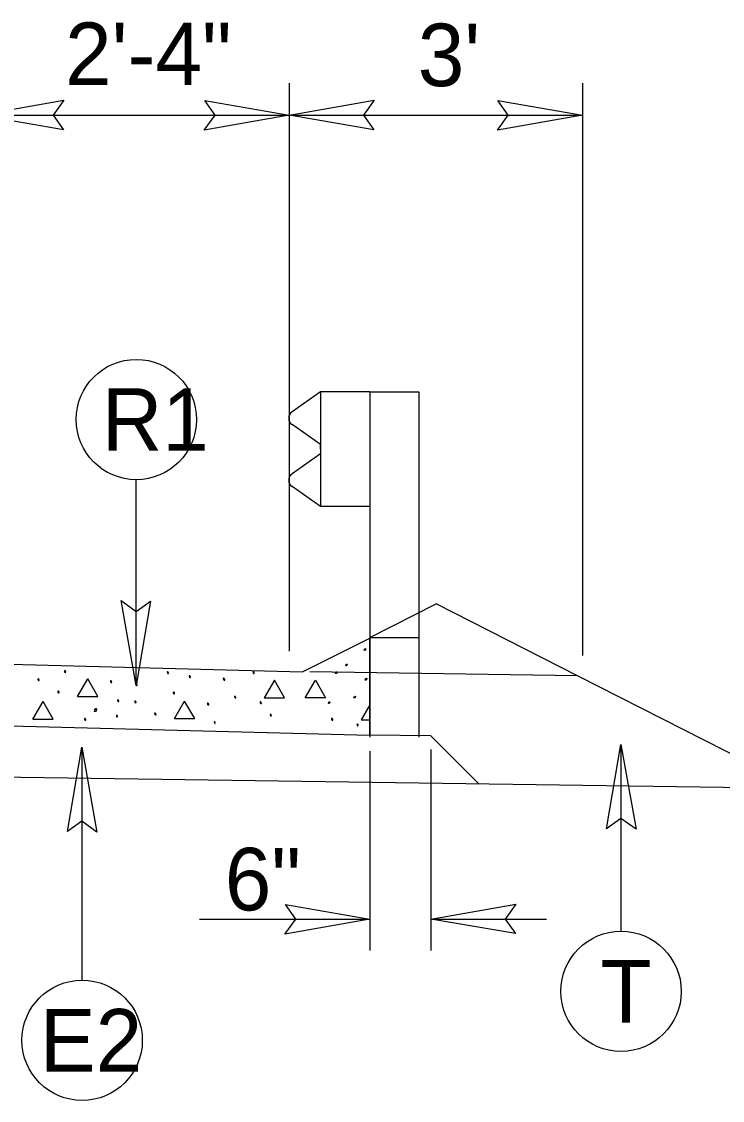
# Model space of a CAD drawing. Extents: x 1553884 to 1554215, y 810431 to 810779.
# Drawn here: x 1554046.03 to 1554057.23, y 810663.89 to 810681.15 of the extents above; entities that cross this region are included whole.
import ezdxf

# ---------------------------------------------------------------- set-up
doc = ezdxf.new("R2010")
doc.units = 0
for name, color, linetype in [('Old_Level_1', 7, 'Continuous'), ('Prop CMT Steel Beam Girder', 7, 'Continuous'), ('Prop Shade Light', 7, 'Continuous'), ('Typical Detail Pavement Repair CELL', 7, 'Continuous'), ('Typical Guardrail CELL', 7, 'Continuous'), ('Typical Pavement Slope Information CELL', 7, 'Continuous'), ('Typical Text ID Circle CELL', 7, 'Continuous')]:
    doc.layers.add(name, color=color, linetype=linetype)

msp = doc.modelspace()

# ---------------------------------------------------------------- linework, layer by layer
at = {"layer": 'Old_Level_1'}
for p, q in [((1554050.307, 810680.165), (1554050.307, 810671.075)), ((1554054.993, 810680.165), (1554054.993, 810671.007)), ((1554045.346, 810679.651), (1554050.307, 810679.651)), ((1554050.307, 810679.651), (1554054.993, 810679.651)), ((1554051.595, 810671.296), (1554052.655, 810671.836)), ((1554054.916, 810670.684), (1554052.655, 810671.836)), ((1554051.506, 810671.092), (1554051.511, 810671.107)), ((1554051.511, 810671.107), (1554051.52, 810671.112)), ((1554051.512, 810671.11), (1554051.517, 810671.114)), ((1554051.517, 810671.114), (1554051.525, 810671.117)), ((1554051.525, 810671.117), (1554051.528, 810671.11)), ((1554051.526, 810671.106), (1554051.525, 810671.093)), ((1554051.528, 810671.106), (1554051.526, 810671.106)), ((1554051.528, 810671.11), (1554051.528, 810671.106)), ((1554051.506, 810671.09), (1554051.506, 810671.092)), ((1554051.517, 810671.087), (1554051.506, 810671.09)), ((1554051.525, 810671.093), (1554051.517, 810671.087)), ((1554046.716, 810670.765), (1554046.713, 810670.759)), ((1554046.713, 810670.759), (1554046.713, 810670.754)), ((1554046.713, 810670.754), (1554046.715, 810670.754)), ((1554046.715, 810670.754), (1554046.716, 810670.743)), ((1554046.725, 810670.764), (1554046.716, 810670.765)), ((1554046.73, 810670.758), (1554046.721, 810670.761)), ((1554046.729, 810670.759), (1554046.725, 810670.764)), ((1554046.735, 810670.74), (1554046.73, 810670.758)), ((1554051.212, 810670.847), (1554051.215, 810670.862)), ((1554051.212, 810670.845), (1554051.212, 810670.847)), ((1554051.221, 810670.842), (1554051.212, 810670.845)), ((1554051.215, 810670.862), (1554051.226, 810670.867)), ((1554051.218, 810670.865), (1554051.221, 810670.868)), ((1554051.221, 810670.868), (1554051.229, 810670.871)), ((1554051.229, 810670.848), (1554051.221, 810670.842)), ((1554051.229, 810670.871), (1554051.234, 810670.865)), ((1554051.232, 810670.861), (1554051.229, 810670.848)), ((1554051.234, 810670.861), (1554051.232, 810670.861)), ((1554051.234, 810670.865), (1554051.234, 810670.861)), ((1554046.293, 810670.634), (1554046.288, 810670.628)), ((1554046.288, 810670.628), (1554046.288, 810670.625)), ((1554046.288, 810670.625), (1554046.29, 810670.625)), ((1554046.29, 810670.625), (1554046.293, 810670.612)), ((1554046.301, 810670.633), (1554046.293, 810670.634)), ((1554046.293, 810670.612), (1554046.301, 810670.606)), ((1554046.307, 810670.626), (1554046.296, 810670.631)), ((1554046.304, 810670.628), (1554046.301, 810670.633)), ((1554046.301, 810670.606), (1554046.31, 810670.607)), ((1554046.31, 810670.611), (1554046.307, 810670.626)), ((1554046.31, 810670.607), (1554046.31, 810670.611)), ((1554046.716, 810670.743), (1554046.725, 810670.737)), ((1554046.725, 810670.737), (1554046.735, 810670.739)), ((1554046.735, 810670.739), (1554046.735, 810670.74)), ((1554046.922, 810670.351), (1554047.085, 810670.633)), ((1554047.247, 810670.351), (1554047.085, 810670.633)), ((1554047.452, 810670.601), (1554047.447, 810670.595)), ((1554047.447, 810670.595), (1554047.447, 810670.592)), ((1554047.447, 810670.592), (1554047.45, 810670.592)), ((1554047.45, 810670.592), (1554047.452, 810670.579)), ((1554047.46, 810670.6), (1554047.452, 810670.601)), ((1554047.466, 810670.594), (1554047.455, 810670.598)), ((1554047.464, 810670.595), (1554047.46, 810670.6)), ((1554047.471, 810670.578), (1554047.466, 810670.594)), ((1554048.358, 810670.748), (1554048.353, 810670.742)), ((1554048.353, 810670.742), (1554048.353, 810670.739)), ((1554048.353, 810670.739), (1554048.356, 810670.739)), ((1554048.356, 810670.739), (1554048.358, 810670.726)), ((1554048.366, 810670.747), (1554048.358, 810670.748)), ((1554048.358, 810670.726), (1554048.366, 810670.72)), ((1554048.372, 810670.74), (1554048.361, 810670.745)), ((1554048.37, 810670.742), (1554048.366, 810670.747)), ((1554048.366, 810670.72), (1554048.377, 810670.722)), ((1554048.377, 810670.725), (1554048.372, 810670.74)), ((1554048.377, 810670.722), (1554048.377, 810670.725)), ((1554048.709, 810670.684), (1554048.705, 810670.678)), ((1554048.705, 810670.678), (1554048.705, 810670.673)), ((1554048.705, 810670.673), (1554048.706, 810670.673)), ((1554048.706, 810670.673), (1554048.709, 810670.661)), ((1554048.717, 810670.681), (1554048.709, 810670.684)), ((1554048.709, 810670.661), (1554048.717, 810670.654)), ((1554048.723, 810670.675), (1554048.713, 810670.679)), ((1554048.72, 810670.678), (1554048.717, 810670.681)), ((1554048.717, 810670.654), (1554048.727, 810670.658)), ((1554048.727, 810670.659), (1554048.723, 810670.675)), ((1554048.727, 810670.658), (1554048.727, 810670.659)), ((1554049.256, 810670.644), (1554049.251, 810670.637)), ((1554049.251, 810670.637), (1554049.251, 810670.633)), ((1554049.251, 810670.633), (1554049.255, 810670.633)), ((1554049.255, 810670.633), (1554049.256, 810670.62)), ((1554049.264, 810670.64), (1554049.256, 810670.644)), ((1554049.256, 810670.62), (1554049.264, 810670.614)), ((1554049.27, 810670.634), (1554049.259, 810670.639)), ((1554049.269, 810670.637), (1554049.264, 810670.64)), ((1554049.264, 810670.614), (1554049.275, 810670.615)), ((1554049.275, 810670.619), (1554049.27, 810670.634)), ((1554049.275, 810670.615), (1554049.275, 810670.619)), ((1554049.729, 810670.748), (1554049.725, 810670.742)), ((1554049.725, 810670.742), (1554049.725, 810670.739)), ((1554049.725, 810670.739), (1554049.728, 810670.739)), ((1554049.728, 810670.739), (1554049.729, 810670.726)), ((1554049.737, 810670.747), (1554049.729, 810670.748)), ((1554049.729, 810670.726), (1554049.737, 810670.72)), ((1554049.744, 810670.74), (1554049.734, 810670.745)), ((1554049.742, 810670.742), (1554049.737, 810670.747)), ((1554049.737, 810670.72), (1554049.748, 810670.722)), ((1554049.748, 810670.725), (1554049.744, 810670.74)), ((1554049.748, 810670.722), (1554049.748, 810670.725)), ((1554050.07, 810670.612), (1554049.908, 810670.331)), ((1554050.233, 810670.331), (1554050.07, 810670.612)), ((1554050.564, 810670.331), (1554050.726, 810670.612)), ((1554054.916, 810670.684), (1554050.634, 810670.747)), ((1554050.726, 810670.612), (1554050.889, 810670.331)), ((1554051.048, 810670.725), (1554051.053, 810670.74)), ((1554051.048, 810670.722), (1554051.048, 810670.725)), ((1554051.059, 810670.72), (1554051.048, 810670.722)), ((1554051.053, 810670.74), (1554051.062, 810670.745)), ((1554051.054, 810670.742), (1554051.059, 810670.747)), ((1554051.059, 810670.747), (1554051.067, 810670.748)), ((1554051.067, 810670.726), (1554051.059, 810670.72)), ((1554051.067, 810670.748), (1554051.072, 810670.742)), ((1554051.068, 810670.739), (1554051.067, 810670.726)), ((1554051.072, 810670.739), (1554051.068, 810670.739)), ((1554051.072, 810670.742), (1554051.072, 810670.739)), ((1554051.522, 810670.619), (1554051.526, 810670.634)), ((1554051.522, 810670.615), (1554051.522, 810670.619)), ((1554051.532, 810670.614), (1554051.522, 810670.615)), ((1554051.526, 810670.634), (1554051.535, 810670.639)), ((1554051.528, 810670.637), (1554051.532, 810670.64)), ((1554051.532, 810670.64), (1554051.54, 810670.644)), ((1554051.54, 810670.62), (1554051.532, 810670.614)), ((1554051.54, 810670.644), (1554051.545, 810670.637)), ((1554051.542, 810670.633), (1554051.54, 810670.62)), ((1554051.545, 810670.633), (1554051.542, 810670.633)), ((1554051.545, 810670.637), (1554051.545, 810670.633)), ((1554062.264, 810666.94), (1554054.916, 810670.684)), ((1554046.61, 810670.439), (1554046.607, 810670.433)), ((1554046.607, 810670.433), (1554046.607, 810670.428)), ((1554046.607, 810670.428), (1554046.608, 810670.428)), ((1554046.608, 810670.428), (1554046.61, 810670.415)), ((1554046.619, 810670.437), (1554046.61, 810670.439)), ((1554046.61, 810670.415), (1554046.619, 810670.411)), ((1554046.625, 810670.431), (1554046.614, 810670.434)), ((1554046.622, 810670.433), (1554046.619, 810670.437)), ((1554046.619, 810670.411), (1554046.629, 810670.412)), ((1554046.629, 810670.414), (1554046.625, 810670.431)), ((1554046.629, 810670.412), (1554046.629, 810670.414)), ((1554047.452, 810670.579), (1554047.46, 810670.573)), ((1554047.46, 810670.573), (1554047.471, 810670.575)), ((1554047.471, 810670.575), (1554047.471, 810670.578)), ((1554047.86, 810670.553), (1554047.857, 810670.547)), ((1554047.857, 810670.547), (1554047.857, 810670.542)), ((1554047.857, 810670.542), (1554047.858, 810670.542)), ((1554047.858, 810670.542), (1554047.86, 810670.531)), ((1554047.867, 810670.551), (1554047.86, 810670.553)), ((1554047.86, 810670.531), (1554047.867, 810670.525)), ((1554047.874, 810670.545), (1554047.864, 810670.548)), ((1554047.872, 810670.547), (1554047.867, 810670.551)), ((1554047.867, 810670.525), (1554047.878, 810670.526)), ((1554047.878, 810670.528), (1554047.874, 810670.545)), ((1554047.878, 810670.526), (1554047.878, 810670.528)), ((1554048.456, 810670.422), (1554048.452, 810670.415)), ((1554048.452, 810670.415), (1554048.452, 810670.412)), ((1554048.452, 810670.412), (1554048.453, 810670.412)), ((1554048.453, 810670.412), (1554048.456, 810670.4)), ((1554048.464, 810670.42), (1554048.456, 810670.422)), ((1554048.47, 810670.414), (1554048.459, 810670.419)), ((1554048.467, 810670.415), (1554048.464, 810670.42)), ((1554048.474, 810670.398), (1554048.47, 810670.414)), ((1554046.21, 810669.987), (1554046.372, 810670.269)), ((1554046.535, 810669.987), (1554046.372, 810670.269)), ((1554046.922, 810670.351), (1554047.247, 810670.351)), ((1554047.566, 810670.3), (1554047.561, 810670.294)), ((1554047.561, 810670.294), (1554047.561, 810670.289)), ((1554047.561, 810670.289), (1554047.564, 810670.289)), ((1554047.564, 810670.289), (1554047.566, 810670.278)), ((1554047.574, 810670.298), (1554047.566, 810670.3)), ((1554047.566, 810670.278), (1554047.574, 810670.272)), ((1554047.58, 810670.292), (1554047.569, 810670.295)), ((1554047.578, 810670.294), (1554047.574, 810670.298)), ((1554047.574, 810670.272), (1554047.585, 810670.273)), ((1554047.585, 810670.275), (1554047.58, 810670.292)), ((1554047.585, 810670.273), (1554047.585, 810670.275)), ((1554047.841, 810670.28), (1554047.836, 810670.273)), ((1554047.836, 810670.273), (1554047.836, 810670.27)), ((1554047.836, 810670.27), (1554047.838, 810670.27)), ((1554047.838, 810670.27), (1554047.841, 810670.258)), ((1554047.849, 810670.278), (1554047.841, 810670.28)), ((1554047.841, 810670.258), (1554047.849, 810670.252)), ((1554047.855, 810670.272), (1554047.844, 810670.277)), ((1554047.852, 810670.273), (1554047.849, 810670.278)), ((1554047.849, 810670.252), (1554047.858, 810670.253)), ((1554047.858, 810670.256), (1554047.855, 810670.272)), ((1554047.858, 810670.253), (1554047.858, 810670.256)), ((1554048.456, 810670.4), (1554048.464, 810670.394)), ((1554048.464, 810670.394), (1554048.474, 810670.395)), ((1554048.471, 810669.997), (1554048.633, 810670.278)), ((1554048.474, 810670.395), (1554048.474, 810670.398)), ((1554048.796, 810669.997), (1554048.633, 810670.278)), ((1554049, 810670.247), (1554048.996, 810670.24)), ((1554048.996, 810670.24), (1554048.996, 810670.237)), ((1554048.996, 810670.237), (1554048.999, 810670.237)), ((1554048.999, 810670.237), (1554049, 810670.225)), ((1554049.008, 810670.245), (1554049, 810670.247)), ((1554049.014, 810670.239), (1554049.003, 810670.244)), ((1554049.013, 810670.24), (1554049.008, 810670.245)), ((1554049.019, 810670.223), (1554049.014, 810670.239)), ((1554049.436, 810670.358), (1554049.431, 810670.351)), ((1554049.431, 810670.351), (1554049.431, 810670.347)), ((1554049.431, 810670.347), (1554049.434, 810670.347)), ((1554049.434, 810670.347), (1554049.436, 810670.334)), ((1554049.444, 810670.354), (1554049.436, 810670.358)), ((1554049.436, 810670.334), (1554049.444, 810670.328)), ((1554049.45, 810670.348), (1554049.439, 810670.353)), ((1554049.448, 810670.351), (1554049.444, 810670.354)), ((1554049.444, 810670.328), (1554049.455, 810670.33)), ((1554049.455, 810670.333), (1554049.45, 810670.348)), ((1554049.455, 810670.33), (1554049.455, 810670.333)), ((1554049.844, 810670.267), (1554049.841, 810670.261)), ((1554049.841, 810670.261), (1554049.841, 810670.258)), ((1554049.841, 810670.258), (1554049.842, 810670.258)), ((1554049.842, 810670.258), (1554049.844, 810670.245)), ((1554049.851, 810670.265), (1554049.844, 810670.267)), ((1554049.844, 810670.245), (1554049.851, 810670.239)), ((1554049.858, 810670.259), (1554049.848, 810670.262)), ((1554049.856, 810670.261), (1554049.851, 810670.265)), ((1554049.851, 810670.239), (1554049.862, 810670.24)), ((1554049.862, 810670.242), (1554049.858, 810670.259)), ((1554049.862, 810670.24), (1554049.862, 810670.242)), ((1554049.908, 810670.331), (1554050.233, 810670.331)), ((1554050.889, 810670.331), (1554050.564, 810670.331)), ((1554050.934, 810670.242), (1554050.939, 810670.259)), ((1554050.934, 810670.24), (1554050.934, 810670.242)), ((1554050.945, 810670.239), (1554050.934, 810670.24)), ((1554050.939, 810670.259), (1554050.948, 810670.262)), ((1554050.94, 810670.261), (1554050.945, 810670.265)), ((1554050.945, 810670.265), (1554050.953, 810670.267)), ((1554050.953, 810670.245), (1554050.945, 810670.239)), ((1554050.953, 810670.267), (1554050.956, 810670.261)), ((1554050.954, 810670.258), (1554050.953, 810670.245)), ((1554050.956, 810670.258), (1554050.954, 810670.258)), ((1554050.956, 810670.261), (1554050.956, 810670.258)), ((1554051.342, 810670.333), (1554051.347, 810670.348)), ((1554051.342, 810670.33), (1554051.342, 810670.333)), ((1554051.353, 810670.328), (1554051.342, 810670.33)), ((1554051.347, 810670.348), (1554051.358, 810670.353)), ((1554051.348, 810670.351), (1554051.353, 810670.354)), ((1554051.353, 810670.354), (1554051.361, 810670.358)), ((1554051.361, 810670.334), (1554051.353, 810670.328)), ((1554051.361, 810670.358), (1554051.365, 810670.351)), ((1554051.362, 810670.347), (1554051.361, 810670.334)), ((1554051.365, 810670.347), (1554051.362, 810670.347)), ((1554051.365, 810670.351), (1554051.365, 810670.347)), ((1554047.196, 810670.114), (1554047.197, 810670.129)), ((1554047.199, 810670.111), (1554047.196, 810670.114)), ((1554047.197, 810670.129), (1554047.199, 810670.131)), ((1554047.199, 810670.145), (1554047.204, 810670.153)), ((1554047.199, 810670.147), (1554047.202, 810670.153)), ((1554047.202, 810670.153), (1554047.199, 810670.137)), ((1554047.202, 810670.131), (1554047.199, 810670.147)), ((1554047.199, 810670.126), (1554047.199, 810670.145)), ((1554047.199, 810670.131), (1554047.202, 810670.131)), ((1554047.212, 810670.114), (1554047.199, 810670.111)), ((1554047.204, 810670.153), (1554047.216, 810670.158)), ((1554047.219, 810670.119), (1554047.212, 810670.114)), ((1554047.216, 810670.158), (1554047.222, 810670.158)), ((1554047.218, 810670.144), (1554047.216, 810670.141)), ((1554047.216, 810670.141), (1554047.218, 810670.139)), ((1554047.226, 810670.145), (1554047.218, 810670.144)), ((1554047.218, 810670.139), (1554047.224, 810670.126)), ((1554047.224, 810670.126), (1554047.219, 810670.119)), ((1554047.222, 810670.158), (1554047.226, 810670.153)), ((1554047.226, 810670.153), (1554047.226, 810670.145)), ((1554048.158, 810670.084), (1554048.155, 810670.078)), ((1554048.155, 810670.078), (1554048.155, 810670.073)), ((1554048.155, 810670.073), (1554048.157, 810670.073)), ((1554048.157, 810670.073), (1554048.158, 810670.061)), ((1554048.167, 810670.083), (1554048.158, 810670.084)), ((1554048.174, 810670.076), (1554048.163, 810670.08)), ((1554048.171, 810670.078), (1554048.167, 810670.083)), ((1554048.177, 810670.059), (1554048.174, 810670.076)), ((1554049, 810670.225), (1554049.008, 810670.218)), ((1554049.008, 810670.218), (1554049.019, 810670.22)), ((1554049.019, 810670.22), (1554049.019, 810670.223)), ((1554050.005, 810670.067), (1554050, 810670.061)), ((1554050.012, 810670.065), (1554050.005, 810670.067)), ((1554050.019, 810670.059), (1554050.008, 810670.064)), ((1554050.016, 810670.061), (1554050.012, 810670.065)), ((1554051.595, 810670.217), (1554051.456, 810669.976)), ((1554046.21, 810669.987), (1554046.535, 810669.987)), ((1554047.036, 810670), (1554047.033, 810669.994)), ((1554047.033, 810669.994), (1554047.033, 810669.991)), ((1554047.033, 810669.991), (1554047.035, 810669.991)), ((1554047.035, 810669.991), (1554047.036, 810669.978)), ((1554047.046, 810669.998), (1554047.036, 810670)), ((1554047.036, 810669.978), (1554047.046, 810669.972)), ((1554047.052, 810669.992), (1554047.041, 810669.997)), ((1554047.049, 810669.994), (1554047.046, 810669.998)), ((1554047.046, 810669.972), (1554047.055, 810669.973)), ((1554047.055, 810669.976), (1554047.052, 810669.992)), ((1554047.055, 810669.973), (1554047.055, 810669.976)), ((1554047.546, 810670.052), (1554047.543, 810670.045)), ((1554047.543, 810670.045), (1554047.543, 810670.041)), ((1554047.543, 810670.041), (1554047.544, 810670.041)), ((1554047.544, 810670.041), (1554047.546, 810670.03)), ((1554047.555, 810670.05), (1554047.546, 810670.052)), ((1554047.546, 810670.03), (1554047.555, 810670.023)), ((1554047.561, 810670.044), (1554047.55, 810670.047)), ((1554047.558, 810670.045), (1554047.555, 810670.05)), ((1554047.555, 810670.023), (1554047.564, 810670.025)), ((1554047.564, 810670.026), (1554047.561, 810670.044)), ((1554047.564, 810670.025), (1554047.564, 810670.026)), ((1554048.158, 810670.061), (1554048.167, 810670.056)), ((1554048.167, 810670.056), (1554048.177, 810670.058)), ((1554048.177, 810670.058), (1554048.177, 810670.059)), ((1554048.471, 810669.997), (1554048.796, 810669.997)), ((1554049.114, 810669.945), (1554049.109, 810669.939)), ((1554049.109, 810669.939), (1554049.109, 810669.934)), ((1554049.109, 810669.934), (1554049.113, 810669.934)), ((1554049.113, 810669.934), (1554049.114, 810669.923)), ((1554049.122, 810669.944), (1554049.114, 810669.945)), ((1554049.114, 810669.923), (1554049.122, 810669.917)), ((1554049.128, 810669.937), (1554049.117, 810669.941)), ((1554050, 810670.061), (1554050, 810670.058)), ((1554050, 810670.058), (1554050.002, 810670.058)), ((1554050.002, 810670.058), (1554050.005, 810670.045)), ((1554050.005, 810670.045), (1554050.012, 810670.039)), ((1554050.012, 810670.039), (1554050.022, 810670.041)), ((1554050.022, 810670.044), (1554050.019, 810670.059)), ((1554050.022, 810670.041), (1554050.022, 810670.044)), ((1554050.984, 810670.003), (1554050.98, 810669.997)), ((1554050.98, 810669.997), (1554050.98, 810669.992)), ((1554050.98, 810669.992), (1554050.983, 810669.992)), ((1554050.983, 810669.992), (1554050.984, 810669.98)), ((1554050.992, 810670), (1554050.984, 810670.003)), ((1554050.984, 810669.98), (1554050.992, 810669.973)), ((1554050.998, 810669.994), (1554050.987, 810669.998)), ((1554050.997, 810669.997), (1554050.992, 810670)), ((1554050.992, 810669.973), (1554051.003, 810669.975)), ((1554051.003, 810669.978), (1554050.998, 810669.994)), ((1554051.003, 810669.975), (1554051.003, 810669.978)), ((1554051.392, 810669.912), (1554051.389, 810669.906)), ((1554051.389, 810669.906), (1554051.389, 810669.903)), ((1554051.389, 810669.903), (1554051.391, 810669.903)), ((1554051.391, 810669.903), (1554051.392, 810669.891)), ((1554051.4, 810669.911), (1554051.392, 810669.912)), ((1554051.392, 810669.891), (1554051.4, 810669.884)), ((1554051.406, 810669.905), (1554051.397, 810669.908)), ((1554051.405, 810669.906), (1554051.4, 810669.911)), ((1554051.411, 810669.887), (1554051.406, 810669.905)), ((1554051.456, 810669.976), (1554051.595, 810669.976)), ((1554051.4, 810669.884), (1554051.411, 810669.886)), ((1554051.411, 810669.886), (1554051.411, 810669.887)), ((1554051.595, 810669.478), (1554051.595, 810666.289)), ((1554052.572, 810669.501), (1554052.572, 810666.289)), ((1554058.463, 810668.877), (1554036.949, 810669.189)), ((1554048.871, 810666.791), (1554051.595, 810666.791)), ((1554052.572, 810666.791), (1554054.421, 810666.791))]:
    msp.add_line(p, q, dxfattribs=at)
msp.add_lwpolyline([(1554053.342, 810668.951), (1554052.572, 810669.72), (1554051.595, 810669.734)], dxfattribs=at)
at = {"layer": 'Prop CMT Steel Beam Girder'}
for p, q in [((1554047.859, 810670.527), (1554047.859, 810673.82)), ((1554055.61, 810669.585), (1554055.61, 810666.597)), ((1554046.993, 810669.541), (1554046.993, 810665.813))]:
    msp.add_line(p, q, dxfattribs=at)
at = {"layer": 'Prop Shade Light'}
for p, q in [((1554050.52, 810670.748), (1554051.595, 810671.286)), ((1554051.595, 810669.734), (1554051.595, 810671.286)), ((1554045.346, 810670.879), (1554050.52, 810670.748)), ((1554045.346, 810669.893), (1554051.595, 810669.734))]:
    msp.add_line(p, q, dxfattribs=at)
at = {"layer": 'Typical Guardrail CELL'}
for p, q in [((1554050.809, 810675.223), (1554050.352, 810674.903)), ((1554051.595, 810675.223), (1554050.809, 810675.223)), ((1554050.809, 810675.223), (1554050.809, 810673.391)), ((1554051.595, 810675.223), (1554051.595, 810671.296)), ((1554051.595, 810675.223), (1554052.381, 810675.223)), ((1554052.381, 810675.223), (1554052.381, 810671.296)), ((1554050.809, 810674.381), (1554050.352, 810674.701)), ((1554050.809, 810674.307), (1554050.809, 810674.381)), ((1554050.809, 810674.233), (1554050.352, 810673.912)), ((1554050.809, 810674.307), (1554050.809, 810674.233)), ((1554050.809, 810673.391), (1554050.352, 810673.711)), ((1554051.595, 810673.391), (1554050.809, 810673.391)), ((1554051.595, 810671.296), (1554052.381, 810671.296)), ((1554051.595, 810671.296), (1554051.595, 810669.703)), ((1554052.381, 810671.296), (1554052.381, 810669.703))]:
    msp.add_line(p, q, dxfattribs=at)
for centre, start, end in [((1554050.422, 810674.802), 125.003, 235.0112), ((1554050.422, 810673.812), 125.0059, 235.0366)]:
    msp.add_arc(centre, 0.123, start, end, dxfattribs=at)
at = {"layer": 'Typical Pavement Slope Information CELL'}
for points in [[(1554046.696, 810679.418), (1554045.346, 810679.651), (1554046.703, 810679.891), (1554046.531, 810679.651)], [(1554048.957, 810679.883), (1554050.307, 810679.651), (1554048.949, 810679.411), (1554049.122, 810679.651)], [(1554051.657, 810679.418), (1554050.307, 810679.651), (1554051.664, 810679.891), (1554051.492, 810679.651)], [(1554053.643, 810679.883), (1554054.993, 810679.651), (1554053.636, 810679.411), (1554053.808, 810679.651)], [(1554048.091, 810671.877), (1554047.859, 810670.527), (1554047.619, 810671.885), (1554047.859, 810671.712)], [(1554055.378, 810668.235), (1554055.61, 810669.585), (1554055.85, 810668.227), (1554055.61, 810668.4)], [(1554046.76, 810668.191), (1554046.993, 810669.541), (1554047.233, 810668.183), (1554046.993, 810668.356)], [(1554050.245, 810667.024), (1554051.595, 810666.791), (1554050.237, 810666.551), (1554050.41, 810666.791)], [(1554053.922, 810666.559), (1554052.572, 810666.791), (1554053.93, 810667.031), (1554053.757, 810666.791)]]:
    msp.add_lwpolyline(points, close=True, dxfattribs=at)
at = {"layer": 'Typical Text ID Circle CELL'}
for centre in [(1554047.862, 810674.782), (1554055.611, 810665.635), (1554046.996, 810664.852)]:
    msp.add_circle(centre, 0.962, dxfattribs=at)

# ---------------------------------------------------------------- texts
at = {"layer": 'Old_Level_1'}
for s, p in [('2\'-4"', (1554046.724, 810680.133)), ("3'", (1554052.362, 810680.115)), ('6"', (1554049.277, 810666.93))]:
    msp.add_text(s, height=1, dxfattribs=at).set_placement(p)
at = {"layer": 'Typical Detail Pavement Repair CELL'}
for s, p in [('R1', (1554047.313, 810674.282)), ('T', (1554055.282, 810665.135)), ('E2', (1554046.32, 810664.352))]:
    msp.add_text(s, height=1, dxfattribs=at).set_placement(p)

doc.saveas('drawing.dxf')
